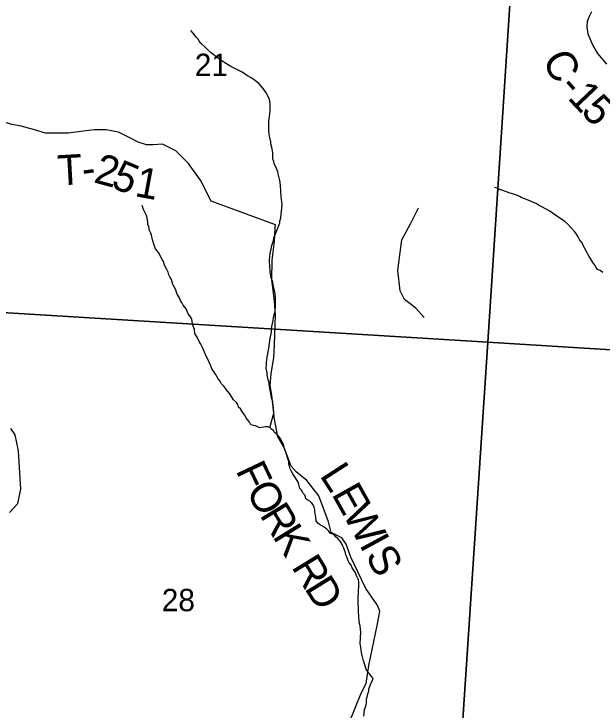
# Model space of a CAD drawing. Extents: x 1949938.81 to 1949945.61, y 152207.65 to 152214.09.
# Drawn here: x 1949941.599 to 1949942.704, y 152210.465 to 152211.771 of the extents above; entities that cross this region are included whole.
import ezdxf

# ---------------------------------------------------------------- set-up
doc = ezdxf.new("R2010")
doc.units = 0
for name, color, linetype in [('GM_X_County_Road', 7, 'Continuous'), ('GM_X_County_Road_Text', 7, 'Continuous'), ('GM_X_Minor_River', 7, 'Continuous'), ('GM_X_Section', 7, 'Continuous'), ('GM_X_Section_Text', 7, 'Continuous'), ('GM_X_Township_Road', 7, 'Continuous'), ('GM_X_Township_Road_Text', 7, 'Continuous'), ('GM_X_Township_ROW', 7, 'Continuous')]:
    doc.layers.add(name, color=color, linetype=linetype)

msp = doc.modelspace()

# ---------------------------------------------------------------- linework, layer by layer
at = {"layer": 'GM_X_County_Road'}
msp.add_lwpolyline([(1949942.6841, 152211.7751), (1949942.6787, 152211.7655), (1949942.6758, 152211.7572), (1949942.675, 152211.7469), (1949942.677, 152211.734), (1949942.6862, 152211.712), (1949942.6949, 152211.6975), (1949942.7119, 152211.6771)], dxfattribs=at)
at = {"layer": 'GM_X_Minor_River'}
for points in [[(1949941.979, 152211.691), (1949941.97, 152211.6984), (1949941.9629, 152211.7046), (1949941.9577, 152211.71), (1949941.9521, 152211.715), (1949941.9487, 152211.7181), (1949941.9458, 152211.7235), (1949941.9425, 152211.7274), (1949941.9362, 152211.7351), (1949941.9317, 152211.7401)], [(1949942.08, 152210.995), (1949942.0873, 152211.0222), (1949942.0874, 152211.0256), (1949942.0871, 152211.0313), (1949942.0854, 152211.0405), (1949942.0854, 152211.0443), (1949942.0833, 152211.0508), (1949942.0815, 152211.0588), (1949942.0805, 152211.0653), (1949942.0788, 152211.0756), (1949942.0785, 152211.0798), (1949942.077, 152211.0847), (1949942.0749, 152211.0943), (1949942.075, 152211.0981), (1949942.0736, 152211.1034), (1949942.0733, 152211.1068), (1949942.0738, 152211.114), (1949942.0738, 152211.1186), (1949942.0743, 152211.1224), (1949942.0751, 152211.1273), (1949942.0773, 152211.1406), (1949942.0781, 152211.144), (1949942.0794, 152211.1531), (1949942.0798, 152211.158), (1949942.0803, 152211.1622), (1949942.0828, 152211.1743), (1949942.0829, 152211.1804), (1949942.0837, 152211.1846), (1949942.0862, 152211.1963), (1949942.0866, 152211.2009), (1949942.0899, 152211.2145), (1949942.0904, 152211.2225), (1949942.0907, 152211.2358), (1949942.0904, 152211.24), (1949942.0897, 152211.2461), (1949942.0887, 152211.2522), (1949942.0862, 152211.2628), (1949942.0856, 152211.2682), (1949942.0827, 152211.2766), (1949942.0806, 152211.2865), (1949942.0806, 152211.2903), (1949942.08, 152211.2975), (1949942.0794, 152211.3086), (1949942.0796, 152211.3162), (1949942.0813, 152211.326), (1949942.0821, 152211.3302), (1949942.0837, 152211.337), (1949942.0865, 152211.3465), (1949942.0874, 152211.351), (1949942.0921, 152211.3616), (1949942.0945, 152211.3684), (1949942.0985, 152211.3793), (1949942.0989, 152211.3827), (1949942.1005, 152211.3888), (1949942.1019, 152211.4017), (1949942.1024, 152211.4066), (1949942.1029, 152211.4146), (1949942.1019, 152211.423), (1949942.1009, 152211.4295), (1949942.1003, 152211.4371), (1949942.1003, 152211.4412), (1949942.1001, 152211.4473), (1949942.0991, 152211.4557), (1949942.0987, 152211.4591), (1949942.0973, 152211.4641), (1949942.0956, 152211.4713), (1949942.0952, 152211.4752), (1949942.0923, 152211.4813), (1949942.0883, 152211.4908), (1949942.0876, 152211.4947), (1949942.0854, 152211.4996), (1949942.0856, 152211.5065), (1949942.0856, 152211.5107), (1949942.0843, 152211.5183), (1949942.0818, 152211.5278), (1949942.0815, 152211.5316), (1949942.079, 152211.5423), (1949942.0787, 152211.5461), (1949942.078, 152211.5526), (1949942.0781, 152211.5568), (1949942.0779, 152211.5663), (1949942.0783, 152211.5697), (1949942.0788, 152211.5739), (1949942.0797, 152211.5837), (1949942.0806, 152211.5905), (1949942.0807, 152211.5993), (1949942.0808, 152211.6027), (1949942.0794, 152211.6115), (1949942.0732, 152211.6233), (1949942.0673, 152211.6314), (1949942.0599, 152211.6403), (1949942.0528, 152211.6461), (1949942.0461, 152211.6512), (1949942.0382, 152211.6551), (1949942.0281, 152211.6621), (1949942.0206, 152211.666), (1949942.0067, 152211.6727), (1949941.9954, 152211.6797), (1949941.9876, 152211.6848), (1949941.979, 152211.691)], [(1949942.7052, 152211.2863), (1949942.6999, 152211.2898), (1949942.6954, 152211.2918), (1949942.6928, 152211.2956), (1949942.6903, 152211.3002), (1949942.6865, 152211.3049), (1949942.6821, 152211.3122), (1949942.6795, 152211.316), (1949942.677, 152211.3206), (1949942.6744, 152211.3256), (1949942.6674, 152211.3379), (1949942.6664, 152211.3421), (1949942.6623, 152211.3471), (1949942.659, 152211.3532), (1949942.656, 152211.3582), (1949942.6527, 152211.3624), (1949942.646, 152211.3702), (1949942.6401, 152211.376), (1949942.6345, 152211.381), (1949942.6277, 152211.386), (1949942.621, 152211.3907), (1949942.6146, 152211.395), (1949942.6057, 152211.4012), (1949942.5974, 152211.4059), (1949942.5918, 152211.4087), (1949942.5847, 152211.4126), (1949942.5802, 152211.4157), (1949942.5719, 152211.4185), (1949942.5651, 152211.4217), (1949942.5568, 152211.4252), (1949942.552, 152211.4272), (1949942.5486, 152211.4288), (1949942.5448, 152211.4304), (1949942.5392, 152211.4324), (1949942.5339, 152211.4344), (1949942.5305, 152211.4352), (1949942.5264, 152211.4368), (1949942.5222, 152211.438), (1949942.5173, 152211.44), (1949942.5117, 152211.442), (1949942.5068, 152211.4443), (1949942.5019, 152211.4459)], [(1949942.1411, 152210.8734), (1949942.1397, 152210.8772), (1949942.1364, 152210.8811), (1949942.1346, 152210.8883), (1949942.1328, 152210.8929), (1949942.1284, 152210.9006), (1949942.1258, 152210.9045), (1949942.1228, 152210.9083), (1949942.1199, 152210.9137), (1949942.1184, 152210.9179), (1949942.117, 152210.9225), (1949942.1155, 152210.9259), (1949942.1153, 152210.9312), (1949942.1131, 152210.9381), (1949942.1117, 152210.9431), (1949942.1099, 152210.9492), (1949942.1081, 152210.9534), (1949942.1063, 152210.9611), (1949942.1049, 152210.9649), (1949942.1016, 152210.9706), (1949942.0997, 152210.9741), (1949942.0975, 152210.9779), (1949942.0934, 152210.9822), (1949942.0886, 152210.9861), (1949942.0871, 152210.9899), (1949942.0834, 152210.9915), (1949942.08, 152210.995), (1949942.0759, 152210.9965), (1949942.0717, 152210.9966), (1949942.0679, 152210.9959), (1949942.0645, 152210.9952), (1949942.0603, 152210.9945), (1949942.0562, 152210.9973), (1949942.0524, 152210.9985), (1949942.0445, 152211.0001), (1949942.0419, 152211.0055), (1949942.0382, 152211.0101), (1949942.0349, 152211.014), (1949942.0327, 152211.0182), (1949942.0286, 152211.024), (1949942.025, 152211.0305), (1949942.0212, 152211.0336), (1949942.0198, 152211.0382), (1949942.0176, 152211.042), (1949942.0116, 152211.047), (1949942.005, 152211.0586), (1949941.9976, 152211.0663), (1949941.9939, 152211.0724), (1949941.9894, 152211.0775), (1949941.9868, 152211.0821), (1949941.9831, 152211.0863), (1949941.978, 152211.0955), (1949941.9743, 152211.1013), (1949941.971, 152211.1055), (1949941.9684, 152211.1124), (1949941.963, 152211.125), (1949941.9604, 152211.1293), (1949941.9586, 152211.1335), (1949941.9535, 152211.1457), (1949941.9506, 152211.1515), (1949941.948, 152211.1553), (1949941.9432, 152211.1645), (1949941.9392, 152211.1718), (1949941.9382, 152211.1791), (1949941.9353, 152211.1871), (1949941.9332, 152211.1981), (1949941.9314, 152211.2024), (1949941.9266, 152211.2089), (1949941.9229, 152211.2181), (1949941.917, 152211.225), (1949941.9148, 152211.2296), (1949941.9122, 152211.2331), (1949941.9104, 152211.2388), (1949941.9056, 152211.2457), (1949941.9027, 152211.2549), (1949941.898, 152211.2634), (1949941.8951, 152211.2733), (1949941.8929, 152211.2771), (1949941.89, 152211.2817), (1949941.8889, 152211.2867), (1949941.8867, 152211.2921), (1949941.8823, 152211.2997), (1949941.8802, 152211.3066), (1949941.8776, 152211.3108), (1949941.871, 152211.3235), (1949941.8677, 152211.3273), (1949941.8654, 152211.3308), (1949941.8622, 152211.3392), (1949941.8611, 152211.3438), (1949941.8597, 152211.3476), (1949941.8576, 152211.3564), (1949941.8565, 152211.3598), (1949941.8539, 152211.3652), (1949941.8525, 152211.3717), (1949941.8507, 152211.3763), (1949941.8508, 152211.3805), (1949941.8498, 152211.3885), (1949941.848, 152211.3934), (1949941.8425, 152211.4045), (1949941.84, 152211.4118)], [(1949942.2562, 152210.4532), (1949942.2579, 152210.4653), (1949942.2607, 152210.4748), (1949942.2615, 152210.4786), (1949942.2616, 152210.4858), (1949942.2625, 152210.4892), (1949942.2637, 152210.4953), (1949942.2657, 152210.5002), (1949942.2661, 152210.504), (1949942.2694, 152210.5149), (1949942.2725, 152210.5202), (1949942.2737, 152210.5244), (1949942.2707, 152210.5282), (1949942.2674, 152210.5325), (1949942.2644, 152210.5359), (1949942.2607, 152210.5409), (1949942.2593, 152210.5455), (1949942.2582, 152210.5497), (1949942.2557, 152210.5574), (1949942.2546, 152210.5623), (1949942.2529, 152210.5696), (1949942.2522, 152210.573), (1949942.2511, 152210.578), (1949942.2505, 152210.5822), (1949942.2498, 152210.5898), (1949942.25, 152210.6008), (1949942.2506, 152210.6111), (1949942.2503, 152210.6157), (1949942.2493, 152210.6233), (1949942.2479, 152210.6301), (1949942.2476, 152210.6336), (1949942.2469, 152210.6389), (1949942.247, 152210.6438), (1949942.2467, 152210.6473), (1949942.2461, 152210.6587), (1949942.2458, 152210.6633), (1949942.2456, 152210.6724), (1949942.2457, 152210.6762), (1949942.2462, 152210.6857), (1949942.2463, 152210.6891), (1949942.2468, 152210.6971), (1949942.2469, 152210.7055), (1949942.2462, 152210.7093), (1949942.2433, 152210.7154), (1949942.2408, 152210.7223), (1949942.2371, 152210.7281), (1949942.2345, 152210.7319), (1949942.2327, 152210.7369), (1949942.229, 152210.7411), (1949942.2268, 152210.745), (1949942.2246, 152210.7526), (1949942.2224, 152210.7564), (1949942.2217, 152210.7599), (1949942.2189, 152210.7687), (1949942.2167, 152210.7725), (1949942.2145, 152210.7779), (1949942.2119, 152210.7821), (1949942.2078, 152210.7867), (1949942.2044, 152210.7894), (1949942.2007, 152210.7941), (1949942.1932, 152210.7972), (1949942.1903, 152210.8015), (1949942.1865, 152210.805), (1949942.1824, 152210.8073), (1949942.1791, 152210.81), (1949942.1734, 152210.8135), (1949942.1701, 152210.8159), (1949942.1671, 152210.8201), (1949942.1661, 152210.8255), (1949942.1654, 152210.8312), (1949942.1647, 152210.8365), (1949942.1641, 152210.8407), (1949942.163, 152210.8457), (1949942.1612, 152210.8499), (1949942.159, 152210.8533), (1949942.1552, 152210.8568), (1949942.1515, 152210.8588), (1949942.1477, 152210.8611), (1949942.146, 152210.8676), (1949942.1411, 152210.8734)]]:
    msp.add_lwpolyline(points, dxfattribs=at)
at = {"layer": 'GM_X_Section'}
for points in [[(1949941.4524, 152212.2232), (1949942.5545, 152212.1539), (1949942.4891, 152211.1555), (1949941.3926, 152211.2226)], [(1949942.5545, 152212.1539), (1949943.6665, 152212.0918), (1949943.6063, 152211.0859), (1949942.4891, 152211.1555)], [(1949942.4891, 152211.1555), (1949942.4221, 152210.1447), (1949941.3344, 152210.2133), (1949941.3926, 152211.2226)], [(1949943.6063, 152211.0859), (1949943.5439, 152210.0754), (1949942.4221, 152210.1447), (1949942.4891, 152211.1555)]]:
    msp.add_lwpolyline(points, close=True, dxfattribs=at)
at = {"layer": 'GM_X_Township_Road'}
for points in [[(1949941.965, 152211.4296), (1949941.9509, 152211.4578), (1949941.9272, 152211.491), (1949941.9035, 152211.5147), (1949941.8782, 152211.5273), (1949941.8608, 152211.5258), (1949941.8482, 152211.5258), (1949941.8324, 152211.5305), (1949941.8181, 152211.5384), (1949941.796, 152211.5495), (1949941.7723, 152211.5542), (1949941.7502, 152211.5542), (1949941.7249, 152211.5511), (1949941.7012, 152211.5479), (1949941.6585, 152211.5479), (1949941.638, 152211.5542), (1949941.6127, 152211.5605), (1949941.5953, 152211.5637), (1949941.5763, 152211.57), (1949941.54, 152211.5769)], [(1949942.2814, 152210.6236), (1949942.2826, 152210.6297), (1949942.2863, 152210.6503), (1949942.2813, 152210.6626), (1949942.2717, 152210.6768), (1949942.2602, 152210.6928), (1949942.252, 152210.7102), (1949942.2319, 152210.7518), (1949942.2232, 152210.7764), (1949942.215, 152210.7883), (1949942.1952, 152210.7982), (1949942.1903, 152210.8184), (1949942.1721, 152210.867), (1949942.1494, 152210.8955), (1949942.1293, 152210.9119), (1949942.1198, 152210.9225), (1949942.1077, 152210.956), (1949942.0948, 152210.978), (1949942.0884, 152211.0111), (1949942.0835, 152211.0559), (1949942.0808, 152211.0738), (1949942.0827, 152211.0958), (1949942.0873, 152211.1266), (1949942.0884, 152211.1505), (1949942.0903, 152211.2067), (1949942.0884, 152211.2326), (1949942.0835, 152211.2725), (1949942.0843, 152211.3093), (1949942.0884, 152211.3443), (1949942.09, 152211.3703)], [(1949941.591, 152210.8357), (1949941.6066, 152210.8524), (1949941.6122, 152210.8794), (1949941.6077, 152210.9516), (1949941.6017, 152210.9816), (1949941.5933, 152210.9934)], [(1949942.2006, 152210.1673), (1949942.1981, 152210.1688), (1949942.1842, 152210.1772), (1949942.1759, 152210.1859), (1949942.1709, 152210.1935), (1949942.1637, 152210.219), (1949942.1524, 152210.2346), (1949942.1425, 152210.2494), (1949942.1372, 152210.2703), (1949942.1331, 152210.2897), (1949942.1323, 152210.3064), (1949942.1372, 152210.3209), (1949942.1664, 152210.3512), (1949942.1869, 152210.3714), (1949942.2043, 152210.393), (1949942.23, 152210.444), (1949942.2516, 152210.4968), (1949942.2607, 152210.515), (1949942.2657, 152210.5485), (1949942.2814, 152210.6236)]]:
    msp.add_lwpolyline(points, dxfattribs=at)
at = {"layer": 'GM_X_Township_ROW'}
for points in [[(1949942.09, 152211.3703), (1949942.0903, 152211.3758), (1949941.9699, 152211.4198), (1949941.965, 152211.4296)], [(1949942.3695, 152211.2018), (1949942.3539, 152211.219), (1949942.3326, 152211.2354), (1949942.3244, 152211.2518), (1949942.3203, 152211.2904), (1949942.3277, 152211.3477), (1949942.3449, 152211.3789), (1949942.3588, 152211.4076)]]:
    msp.add_lwpolyline(points, dxfattribs=at)

# ---------------------------------------------------------------- texts
at = {"layer": 'GM_X_County_Road_Text'}
for s, rotation, p in [('C', 297.4188, (1949942.5905, 152211.686)), ('-', 311.1509, (1949942.6203, 152211.6323)), ('1', 313.4805, (1949942.6374, 152211.6129)), ('5', 314.1169, (1949942.662, 152211.587))]:
    msp.add_text(s, height=0.0568, rotation=rotation, dxfattribs=at).set_placement(p)
at = {"layer": 'GM_X_Section_Text'}
for s, p in [('21', (1949941.939, 152211.655)), ('28', (1949941.877, 152210.6505))]:
    msp.add_text(s, height=0.04186, rotation=0, dxfattribs=at).set_placement(p)
at = {"layer": 'GM_X_Township_Road_Text'}
for s, rotation, p in [('T', 3.2256, (1949941.6828, 152211.4494)), ('2', 344.6074, (1949941.7473, 152211.4559)), ('5', 337.0855, (1949941.7792, 152211.4472)), ('1', 349.6165, (1949941.8244, 152211.4297)), ('-', 7.9157, (1949941.7303, 152211.4523)), ('F', 295.4616, (1949942.015, 152210.9147)), ('L', 302.7784, (1949942.1725, 152210.9054)), ('O', 300.1858, (1949942.0339, 152210.8756)), ('E', 299.2234, (1949942.195, 152210.8705)), ('R', 301.3419, (1949942.0597, 152210.8313)), ('W', 298.5611, (1949942.2156, 152210.8336)), ('K', 301.5658, (1949942.0841, 152210.7912)), ('I', 298.5583, (1949942.2471, 152210.7757)), ('S', 298.5543, (1949942.2583, 152210.7552)), ('R', 301.5938, (1949942.1194, 152210.7337)), ('D', 301.7555, (1949942.1439, 152210.6938))]:
    msp.add_text(s, height=0.0568, rotation=rotation, dxfattribs=at).set_placement(p)

doc.saveas('drawing.dxf')
